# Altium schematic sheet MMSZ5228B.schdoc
size 127 x 101 mm
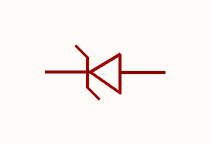
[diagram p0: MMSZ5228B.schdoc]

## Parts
ZD?  mmsz5228b  [SOD-123_L2.8-W1.8-LS3.7-RD]  (value not drawn)

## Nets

Not connected (* = marked no-connect by the designer): ZD? 1(K) 2(A)

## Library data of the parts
ZD? = mmsz5228b: 二极管配置:1个独立式;稳压值(标称值):3.9V;稳压值(范围值):3.71V~4.1V;耗散功率(Pd):350mW;; Manufacturer: CJ(江苏长电/长晶); AddInBom: yes; ModelId: 7884390a25fb4c08947731ebfba7e3f8; ModelTransform: 144.8816,62.992,0,0,0,0,0,0,0; Diode Configuration: 1个独立式; Zener Voltage(Nom): 3.9V; Reverse Leakage Current (Ir): 10uA@1V; Pd - Power Dissipation: 350mW; Impedance(Zzt): 23Ω; Impedance(Zzk): 1.9kΩ; Operating Junction Temperature Range: -65℃~+150℃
